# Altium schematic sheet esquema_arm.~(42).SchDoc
size A4
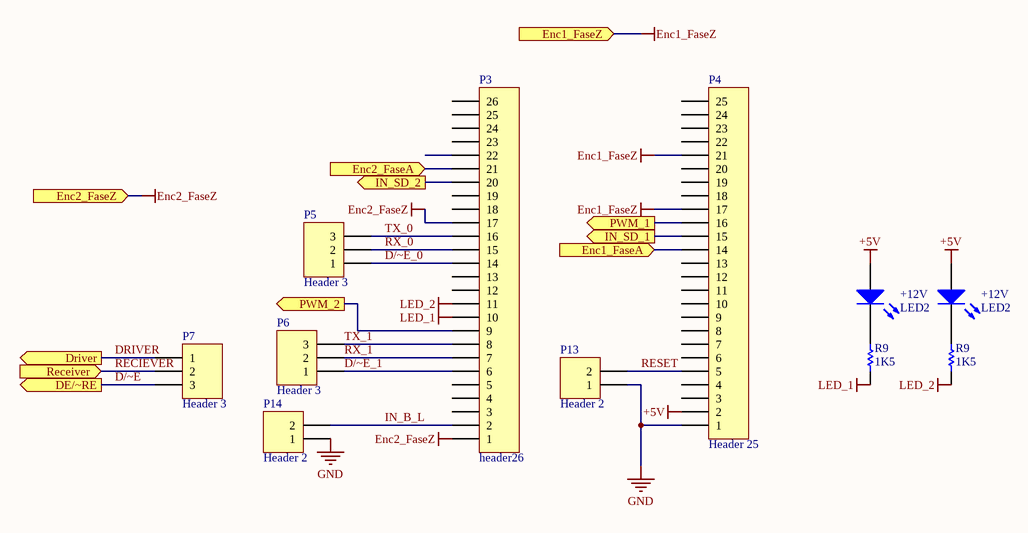
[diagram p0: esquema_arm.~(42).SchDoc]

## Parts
(Parts that share a designator on the sheet are numbered #1, #2 ... from top to bottom, then left to right.)
+12V#1  LED2  [CAPPR2.5-6.3X5]
+12V#2  LED2  [CAPPR2.5-6.3X5]
P3  header26  [HDR1x26]
P4  Header 25  [HDR1X25]
P5  Header 3  [HDR1X3]
P6  Header 3  [HDR1X3]
P7  Header 3  [HDR1X3]
P13  Header 2  [wf2s]
P14  Header 2  [wf2s]
R9#1  value 1K5  [AXIAL-0.3]  (hidden comment: Carbon 1/8w 5%)
R9#2  value 1K5  [AXIAL-0.3]  (hidden comment: Carbon 1/8w 5%)

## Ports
DE/~RE (out), Driver (out), Enc1_FaseA (in), Enc1_FaseZ (in), Enc2_FaseA (in), Enc2_FaseZ (in), IN_SD_1 (out), IN_SD_2 (out), PWM_1 (out), PWM_2 (out), Receiver (in)

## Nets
+5V: +12V#1.1(A) +12V#2.1(A) P4.2
Enc1_FaseZ: P4.17 P4.21 ; port Enc1_FaseZ
Enc2_FaseZ: P3.1 P3.17 ; port Enc2_FaseZ
GND: P4.1 P13.1 P14.1
LED_1: P3.10 R9#1.2
LED_2: P3.11 R9#2.2
D/~E: P7.3 ; port DE/~RE
D/~E_0: P3.14 P5.1
D/~E_1: P3.6 P6.1
DRIVER: P7.1 ; port Driver
Enc1_FaseA: P4.14 ; port Enc1_FaseA
Enc2_FaseA: P3.21 ; port Enc2_FaseA
IN_B_L: P3.2 P14.2
IN_SD_1: P4.15 ; port IN_SD_1
IN_SD_2: P3.20 ; port IN_SD_2
PWM_1: P4.16 ; port PWM_1
PWM_2: P3.9 ; port PWM_2
RECIEVER: P7.2 ; port Receiver
RESET: P4.5 P13.2
RX_0: P3.15 P5.2
RX_1: P3.7 P6.2
TX_0: P3.16 P5.3
TX_1: P3.8 P6.3
Net+12V#1_2: +12V#1.2(K) R9#1.1
Net+12V#2_2: +12V#2.2(K) R9#2.1

Not connected (* = marked no-connect by the designer): P3 3 4 5 12 13 18 19 22 23 24 25 26; P4 3 4 6 7 8 9 10 11 12 13 18 19 20 22 23 24 25

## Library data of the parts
+12V#1 +12V#2 = LED2: Typical RED, GREEN, YELLOW, AMBER GaAs LED
P3 = Component_1
P4 = Header 25: Header, 25-Pin
P5-P7 = Header 3: Header, 3-Pin
P13 P14 = Header 2: Header, 2-Pin
R9#1 R9#2 = Res Semi: Semiconductor Resistor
